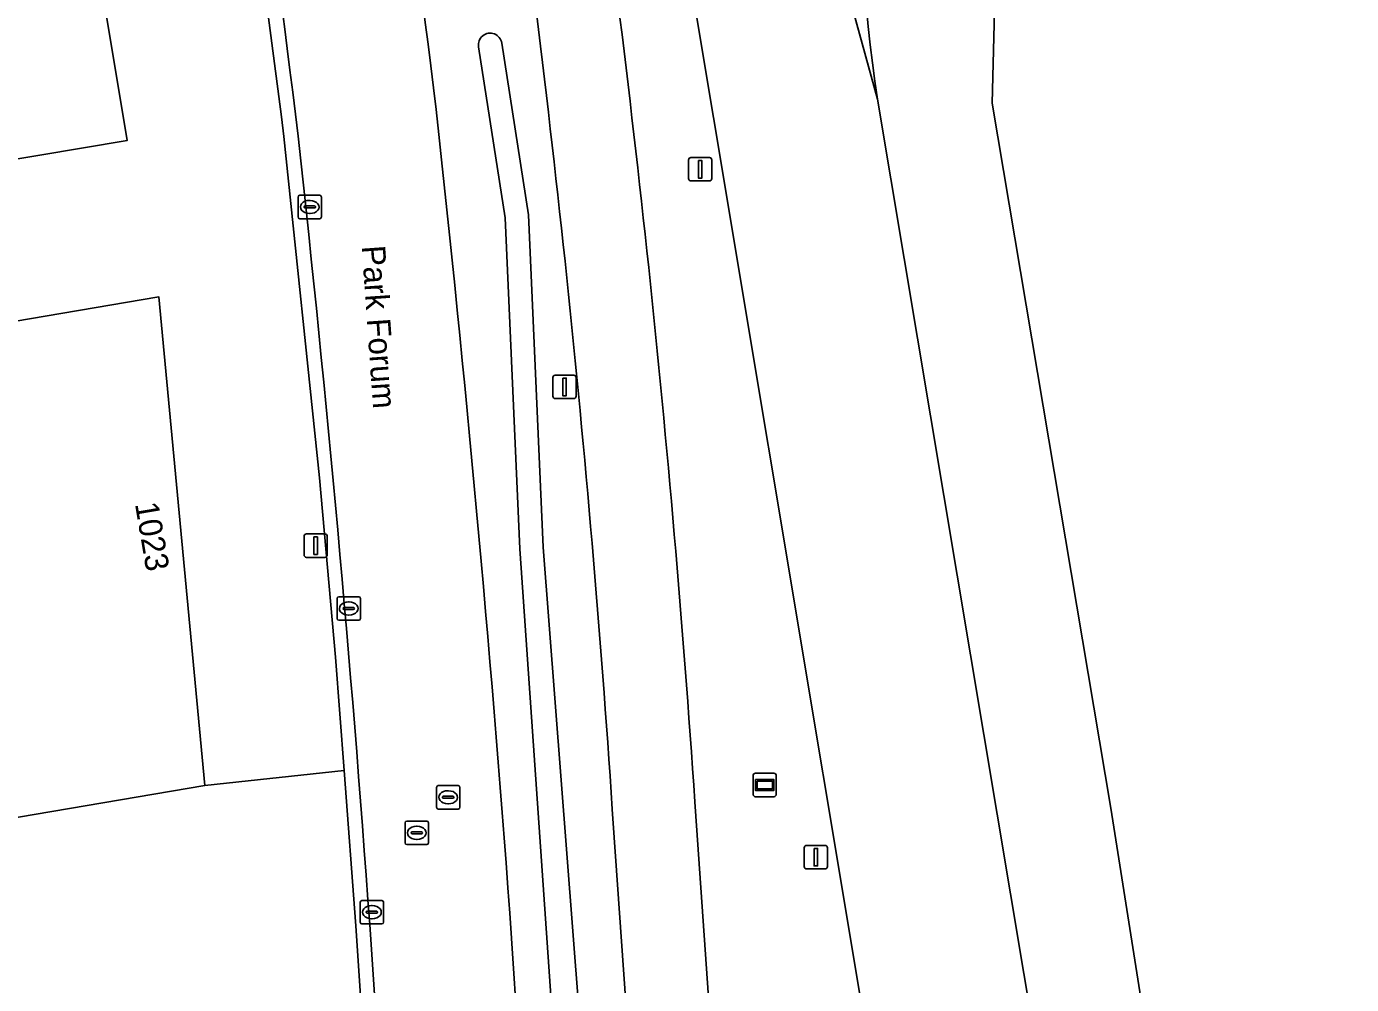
# Model space of a CAD drawing. Extents: x 154324 to 155744, y 382937 to 384188.
# Drawn here: x 155052.1 to 155108.8, y 383387.4 to 383428.3 of the extents above; entities that cross this region are included whole.
import ezdxf

# ---------------------------------------------------------------- set-up
doc = ezdxf.new("R2010")
doc.units = 0
for name, color, linetype in [('IMGEO_Berm_groen', 7, 'Continuous'), ('IMGEO_Erf', 7, 'Continuous'), ('IMGEO_Fietspad_gesloten', 7, 'Continuous'), ('IMGEO_Grasland_agrarisch', 7, 'Continuous'), ('IMGEO_Greppel_droge_sloot', 7, 'Continuous'), ('IMGEO_Groenvoorziening', 7, 'Continuous'), ('IMGEO_Kolk', 7, 'Continuous'), ('IMGEO_Lichtmast', 7, 'Continuous'), ('IMGEO_Loofbos', 7, 'Continuous'), ('IMGEO_Openbare_ruimte_label', 7, 'Continuous'), ('IMGEO_Pand', 7, 'Continuous'), ('IMGEO_Pand_nummerreeks', 7, 'Continuous'), ('IMGEO_Rijbaan_lokaal_gesloten', 7, 'Continuous'), ('IMGEO_Rijbaan_lokaal_open', 7, 'Continuous'), ('IMGEO_Rijbaan_regionaal_gesloten', 7, 'Continuous'), ('IMGEO_Rioolput', 7, 'Continuous'), ('IMGEO_Wegwijzer', 7, 'Continuous')]:
    doc.layers.add(name, color=color, linetype=linetype)

msp = doc.modelspace()

# ---------------------------------------------------------------- linework, layer by layer
at = {"layer": 'IMGEO_Berm_groen'}
for points in [[(155080.698, 383395.149), (155084.447, 383341.596), (155085.067, 383327.696), (155085.135, 383323.941), (155087.898, 383324.309), (155095.535, 383325.326), (155097.848, 383325.634), (155095.519, 383340.332), (155076.819, 383452.367)], [(155076.041, 383365.341), (155073.219, 383405.951), (155072.594, 383420.096), (155071.455, 383427.398)], [(155072.443, 383427.552), (155073.586, 383420.223), (155074.216, 383406.02)], [(155074.216, 383406.02), (155075.741, 383386.313), (155077.04, 383365.403)], [(155081.9, 383290.584), (155081.827, 383312.283), (155081.566, 383327.494), (155080.905, 383341.835), (155077.17, 383394.842)], [(155072.788, 383390.399), (155076.503, 383334.279)]]:
    msp.add_lwpolyline(points, dxfattribs=at)
for centre, radius, start, end in [((154416.191, 383345.471), 658.237, 6.914298, 9.527814), ((154487.454, 383355.336), 594.578, 3.839363, 8.252921), ((154487.732, 383355.709), 590.736, 3.798282, 8.215646), ((155071.949, 383427.475), 0.5, 8.8525, 188.8663), ((154136.569, 383321.838), 938.726, 4.1884, 6.291685)]:
    msp.add_arc(centre, radius, start, end, dxfattribs=at)
at = {"layer": 'IMGEO_Erf'}
for points in [[(155009.132, 383408.441), (155057.795, 383416.713), (155059.756, 383395.855), (155065.709, 383396.485), (155065.341, 383401.33), (155064.659, 383408.986), (155063.139, 383423.564), (155063.03, 383424.403), (155061.613, 383435.27), (155060.487, 383443.041), (155058.846, 383453.397), (155045.918, 383530.449)], [(155044.545, 383443.936), (155052.777, 383445.305), (155054.28, 383436.31), (155053.008, 383436.097), (155053.665, 383432.17), (155054.937, 383432.384), (155056.445, 383423.395), (154989.658, 383412.19)]]:
    msp.add_lwpolyline(points, dxfattribs=at)
at = {"layer": 'IMGEO_Fietspad_gesloten'}
for points in [[(155077.17, 383394.842), (155080.905, 383341.835), (155081.566, 383327.494), (155081.827, 383312.283), (155081.9, 383290.584)], [(155085.424, 383290.508), (155085.346, 383312.247), (155085.135, 383323.941), (155085.067, 383327.696), (155084.447, 383341.596), (155080.698, 383395.149)]]:
    msp.add_lwpolyline(points, dxfattribs=at)
for centre, radius, start, end in [((154487.454, 383355.336), 594.578, 3.839363, 8.252921), ((154487.732, 383355.709), 590.736, 3.798282, 8.215646)]:
    msp.add_arc(centre, radius, start, end, dxfattribs=at)
at = {"layer": 'IMGEO_Grasland_agrarisch'}
msp.add_lwpolyline([(155069.432, 383341.538), (155066.213, 383389.857), (155065.709, 383396.485), (155059.756, 383395.855), (155012.632, 383387.85), (154994.323, 383384.618), (154989.658, 383412.19), (154987.442, 383425.439), (154984.951, 383439.946), (154985.613, 383440.023), (154982.63, 383457.869), (154982.713, 383457.883), (154949.335, 383647.913)], dxfattribs=at)
at = {"layer": 'IMGEO_Greppel_droge_sloot'}
for points in [[(155071.455, 383427.398), (155072.594, 383420.096), (155073.219, 383405.951), (155076.041, 383365.341)], [(155077.04, 383365.403), (155075.741, 383386.313), (155074.216, 383406.02), (155073.586, 383420.223), (155072.443, 383427.552)]]:
    msp.add_lwpolyline(points, dxfattribs=at)
msp.add_arc((155071.949, 383427.475), 0.5, 8.8525, 188.8663, dxfattribs=at)
at = {"layer": 'IMGEO_Groenvoorziening'}
msp.add_lwpolyline([(155098.468, 383394.88), (155093.402, 383424.985), (155093.91, 383445.3), (155100.943, 383462.488), (155107.736, 383471.089), (155129.143, 383483.74), (155137.144, 383484.281), (155140.63, 383467.071), (155136.381, 383463.412), (155137.911, 383457.313), (155135.315, 383439.71), (155145.951, 383434.989), (155156.14, 383427.969), (155169.731, 383420.841), (155156.553, 383398.835), (155144.405, 383376.88), (155136.829, 383369.749), (155130.45, 383360.745), (155130.039, 383352.225), (155124.389, 383342.473), (155103.488, 383363.139)], close=True, dxfattribs=at)
msp.add_lwpolyline([(155088.506, 383425.158), (155097.016, 383374.301)], dxfattribs=at)
msp.add_arc((155150.9, 383434.774), 63.13, 166.13008, 188.76182, dxfattribs=at)
at = {"layer": 'IMGEO_Kolk'}
for p, q in [((155063.742, 383420.127), (155063.742, 383420.979)), ((155063.817, 383421.053), (155064.669, 383421.053)), ((155064.743, 383420.979), (155064.743, 383420.127)), ((155064.001, 383420.547), (155064.001, 383420.559)), ((155064.439, 383420.51), (155064.041, 383420.51)), ((155064.044, 383420.596), (155064.442, 383420.596)), ((155064.23, 383420.833), (155064.255, 383420.833)), ((155064.485, 383420.559), (155064.485, 383420.547)), ((155064.669, 383420.053), (155063.817, 383420.053)), ((155064.253, 383420.273), (155064.228, 383420.273)), ((155065.481, 383403.906), (155066.333, 383403.906)), ((155065.406, 383402.98), (155065.406, 383403.832)), ((155065.665, 383403.4), (155065.665, 383403.412)), ((155066.103, 383403.363), (155065.705, 383403.363)), ((155065.708, 383403.449), (155066.106, 383403.449)), ((155065.894, 383403.686), (155065.919, 383403.686)), ((155066.149, 383403.412), (155066.149, 383403.4)), ((155066.407, 383403.832), (155066.407, 383402.98)), ((155066.333, 383402.906), (155065.481, 383402.906)), ((155065.917, 383403.126), (155065.892, 383403.126)), ((155066.397, 383390.012), (155066.397, 383390.864)), ((155066.472, 383390.938), (155067.324, 383390.938)), ((155067.398, 383390.864), (155067.398, 383390.012)), ((155066.656, 383390.432), (155066.656, 383390.444)), ((155067.094, 383390.395), (155066.696, 383390.395)), ((155066.699, 383390.481), (155067.097, 383390.481)), ((155066.885, 383390.718), (155066.91, 383390.718)), ((155067.14, 383390.444), (155067.14, 383390.432)), ((155067.324, 383389.938), (155066.472, 383389.938)), ((155066.908, 383390.158), (155066.883, 383390.158))]:
    msp.add_line(p, q, dxfattribs=at)
for points in [[(155063.742, 383420.127), (155063.742, 383420.979)], [(155063.817, 383421.053), (155064.669, 383421.053)], [(155064.743, 383420.979), (155064.743, 383420.127)], [(155064.669, 383420.053), (155063.817, 383420.053)], [(155065.481, 383403.906), (155066.333, 383403.906)], [(155065.406, 383402.98), (155065.406, 383403.832)], [(155066.407, 383403.832), (155066.407, 383402.98)], [(155066.333, 383402.906), (155065.481, 383402.906)], [(155066.397, 383390.012), (155066.397, 383390.864)], [(155066.472, 383390.938), (155067.324, 383390.938)], [(155067.398, 383390.864), (155067.398, 383390.012)], [(155067.324, 383389.938), (155066.472, 383389.938)]]:
    msp.add_lwpolyline(points, dxfattribs=at)
for centre, radius, start, end in [((155063.819, 383420.977), 0.0765, 91.552, 178.448), ((155063.819, 383420.977), 0.0765, 91.552, 178.448), ((155064.667, 383420.977), 0.0765, 1.552, 88.448), ((155064.667, 383420.977), 0.0765, 1.552, 88.448), ((155064.041, 383420.556), 0.0403, 85.8775, 175.7526), ((155064.038, 383420.546), 0.0366, 178.938, 274.7102), ((155064.442, 383420.553), 0.043, 264.8664, 352.4533), ((155064.446, 383420.558), 0.0386, 1.7309, 96.639), ((155063.819, 383420.129), 0.0765, 181.552, 268.448), ((155063.819, 383420.129), 0.0765, 181.552, 268.448), ((155064.667, 383420.129), 0.0765, 271.552, 358.448), ((155064.667, 383420.129), 0.0765, 271.552, 358.448), ((155065.483, 383403.83), 0.0765, 91.552, 178.448), ((155065.483, 383403.83), 0.0765, 91.552, 178.448), ((155066.331, 383403.83), 0.0765, 1.552, 88.448), ((155066.331, 383403.83), 0.0765, 1.552, 88.448), ((155065.705, 383403.409), 0.0403, 85.8775, 175.7526), ((155065.702, 383403.399), 0.0366, 178.938, 274.7102), ((155066.106, 383403.406), 0.043, 264.8664, 352.4533), ((155066.11, 383403.411), 0.0386, 1.7309, 96.639), ((155065.483, 383402.982), 0.0765, 181.552, 268.448), ((155065.483, 383402.982), 0.0765, 181.552, 268.448), ((155066.331, 383402.982), 0.0765, 271.552, 358.448), ((155066.331, 383402.982), 0.0765, 271.552, 358.448), ((155066.474, 383390.862), 0.0765, 91.552, 178.448), ((155066.474, 383390.862), 0.0765, 91.552, 178.448), ((155067.322, 383390.862), 0.0765, 1.552, 88.448), ((155067.322, 383390.862), 0.0765, 1.552, 88.448), ((155066.696, 383390.441), 0.0403, 85.8775, 175.7526), ((155066.693, 383390.431), 0.0366, 178.938, 274.7102), ((155067.097, 383390.438), 0.043, 264.8664, 352.4533), ((155067.101, 383390.443), 0.0386, 1.7309, 96.639), ((155066.474, 383390.014), 0.0765, 181.552, 268.448), ((155066.474, 383390.014), 0.0765, 181.552, 268.448), ((155067.322, 383390.014), 0.0765, 271.552, 358.448), ((155067.322, 383390.014), 0.0765, 271.552, 358.448)]:
    msp.add_arc(centre, radius, start, end, dxfattribs=at)
for centre, major_axis, ratio, start_param, end_param in [((155064.229, 383420.553), (-0.387, 0.002), 0.722429, 4.712389, 7.853982), ((155064.254, 383420.553), (-0.39, 0.002), 0.717154, 1.570796, 4.712389), ((155065.893, 383403.406), (-0.387, 0.002), 0.722429, 4.712389, 7.853982), ((155065.918, 383403.406), (-0.39, 0.002), 0.717154, 1.570796, 4.712389), ((155066.884, 383390.438), (-0.387, 0.002), 0.722429, 4.712389, 7.853982), ((155066.909, 383390.438), (-0.39, 0.002), 0.717154, 1.570796, 4.712389)]:
    msp.add_ellipse(centre, major_axis=major_axis, ratio=ratio, start_param=start_param, end_param=end_param, dxfattribs=at)
at = {"layer": 'IMGEO_Lichtmast'}
for p, q in [((155080.432, 383421.763), (155080.432, 383422.563)), ((155080.432, 383422.563), (155080.432, 383421.763)), ((155080.532, 383422.663), (155081.322, 383422.663)), ((155081.322, 383422.663), (155080.532, 383422.663)), ((155081.422, 383422.563), (155081.422, 383421.763)), ((155081.422, 383421.763), (155081.422, 383422.563)), ((155081.322, 383421.663), (155080.532, 383421.663)), ((155080.532, 383421.663), (155081.322, 383421.663)), ((155074.631, 383412.47), (155074.631, 383413.27)), ((155074.631, 383413.27), (155074.631, 383412.47)), ((155074.731, 383413.37), (155075.521, 383413.37)), ((155075.521, 383413.37), (155074.731, 383413.37)), ((155075.621, 383413.27), (155075.621, 383412.47)), ((155075.621, 383412.47), (155075.621, 383413.27)), ((155075.521, 383412.37), (155074.731, 383412.37)), ((155074.731, 383412.37), (155075.521, 383412.37)), ((155063.998, 383405.692), (155063.998, 383406.492)), ((155063.998, 383406.492), (155063.998, 383405.692)), ((155064.098, 383406.592), (155064.888, 383406.592)), ((155064.888, 383406.592), (155064.098, 383406.592)), ((155064.988, 383406.492), (155064.988, 383405.692)), ((155064.988, 383405.692), (155064.988, 383406.492)), ((155064.888, 383405.592), (155064.098, 383405.592)), ((155064.098, 383405.592), (155064.888, 383405.592)), ((155085.371, 383392.388), (155085.371, 383393.188)), ((155085.371, 383393.188), (155085.371, 383392.388)), ((155085.471, 383393.288), (155086.261, 383393.288)), ((155086.261, 383393.288), (155085.471, 383393.288)), ((155086.361, 383393.188), (155086.361, 383392.388)), ((155086.361, 383392.388), (155086.361, 383393.188)), ((155086.261, 383392.288), (155085.471, 383392.288)), ((155085.471, 383392.288), (155086.261, 383392.288))]:
    msp.add_line(p, q, dxfattribs=at)
for points in [[(155080.852, 383422.538), (155081.002, 383422.538), (155081.002, 383421.788), (155080.852, 383421.788), (155080.852, 383422.538)], [(155075.051, 383413.245), (155075.201, 383413.245), (155075.201, 383412.495), (155075.051, 383412.495), (155075.051, 383413.245)], [(155064.418, 383406.467), (155064.568, 383406.467), (155064.568, 383405.717), (155064.418, 383405.717), (155064.418, 383406.467)], [(155085.791, 383393.163), (155085.941, 383393.163), (155085.941, 383392.413), (155085.791, 383392.413), (155085.791, 383393.163)]]:
    msp.add_lwpolyline(points, dxfattribs=at)
for centre, start, end in [((155080.532, 383422.563), 90, 180), ((155080.532, 383422.563), 90, 180), ((155081.322, 383422.563), 0, 90), ((155081.322, 383422.563), 360, 90), ((155080.532, 383421.763), 180, 270), ((155080.532, 383421.763), 180, 270), ((155081.322, 383421.763), 270, 0), ((155081.322, 383421.763), 270, 0), ((155074.731, 383413.27), 90, 180), ((155074.731, 383413.27), 90, 180), ((155075.521, 383413.27), 0, 90), ((155075.521, 383413.27), 360, 90), ((155074.731, 383412.47), 180, 270), ((155074.731, 383412.47), 180, 270), ((155075.521, 383412.47), 270, 0), ((155075.521, 383412.47), 270, 0), ((155064.098, 383406.492), 90, 180), ((155064.098, 383406.492), 90, 180), ((155064.888, 383406.492), 0, 90), ((155064.888, 383406.492), 360, 90), ((155064.098, 383405.692), 180, 270), ((155064.098, 383405.692), 180, 270), ((155064.888, 383405.692), 270, 0), ((155064.888, 383405.692), 270, 0), ((155085.471, 383393.188), 90, 180), ((155085.471, 383393.188), 90, 180), ((155086.261, 383393.188), 0, 90), ((155086.261, 383393.188), 360, 90), ((155085.471, 383392.388), 180, 270), ((155085.471, 383392.388), 180, 270), ((155086.261, 383392.388), 270, 0), ((155086.261, 383392.388), 270, 0)]:
    msp.add_arc(centre, 0.1, start, end, dxfattribs=at)
at = {"layer": 'IMGEO_Loofbos'}
msp.add_lwpolyline([(155130.039, 383352.225), (155130.45, 383360.745), (155136.829, 383369.749), (155144.405, 383376.88), (155156.553, 383398.835), (155169.731, 383420.841), (155156.14, 383427.969), (155145.951, 383434.989), (155135.315, 383439.71), (155137.911, 383457.313), (155136.381, 383463.412), (155140.63, 383467.071), (155137.144, 383484.281), (155129.143, 383483.74), (155107.736, 383471.089), (155100.943, 383462.488), (155093.91, 383445.3), (155093.402, 383424.985), (155098.468, 383394.88), (155103.488, 383363.139), (155124.389, 383342.473)], close=True, dxfattribs=at)
at = {"layer": 'IMGEO_Pand'}
for points in [[(155054.937, 383432.384), (155053.665, 383432.17), (155053.008, 383436.097), (155054.28, 383436.31), (155052.777, 383445.305), (155044.545, 383443.936), (155044.599, 383443.611), (155045.151, 383443.703), (155045.605, 383440.97), (155040.407, 383440.106), (155015.086, 383435.797), (155016.017, 383430.255), (154987.442, 383425.439), (154989.658, 383412.19), (155056.445, 383423.395)], [(155057.795, 383416.713), (155009.132, 383408.441), (155012.632, 383387.85), (155059.756, 383395.855)]]:
    msp.add_lwpolyline(points, close=True, dxfattribs=at)
at = {"layer": 'IMGEO_Rijbaan_lokaal_gesloten'}
for points in [[(155076.503, 383334.279), (155072.788, 383390.399)], [(155066.805, 383389.917), (155070.546, 383334.082)]]:
    msp.add_lwpolyline(points, dxfattribs=at)
for centre, radius, start, end in [((154416.191, 383345.471), 658.237, 6.914298, 9.527814), ((154372.74, 383339.354), 696.116, 6.949521, 9.434678), ((154136.569, 383321.838), 938.726, 4.1884, 6.291685), ((154201.434, 383328.122), 867.574, 4.08448, 6.316961)]:
    msp.add_arc(centre, radius, start, end, dxfattribs=at)
at = {"layer": 'IMGEO_Rijbaan_lokaal_open'}
for points in [[(155059.439, 383453.463), (155046.503, 383530.572), (155016.871, 383707.197), (155016.277, 383707.107), (155024.164, 383660.104), (155045.918, 383530.449), (155058.846, 383453.397), (155060.487, 383443.041), (155061.613, 383435.27), (155063.03, 383424.403), (155063.139, 383423.564), (155064.659, 383408.986), (155065.341, 383401.33), (155065.709, 383396.485), (155066.213, 383389.857), (155069.432, 383341.538), (155069.458, 383341.15), (155069.938, 383333.947), (155070.4, 383319.494), (155070.638, 383289.04), (155071.247, 383289.042), (155071.154, 383307.067)], [(155070.546, 383334.082), (155066.805, 383389.917)]]:
    msp.add_lwpolyline(points, dxfattribs=at)
for centre, radius, start, end in [((154372.74, 383339.354), 696.116, 6.949521, 9.434678), ((154201.434, 383328.122), 867.574, 4.08448, 6.316961)]:
    msp.add_arc(centre, radius, start, end, dxfattribs=at)
at = {"layer": 'IMGEO_Rijbaan_regionaal_gesloten'}
for points in [[(155088.506, 383425.158), (155082.147, 383448.215), (155075.664, 383486.308), (155070.593, 383489.047), (155071.187, 383485.369), (155076.819, 383452.367), (155095.519, 383340.332), (155097.848, 383325.634), (155099.567, 383313.904), (155107.952, 383291.229), (155108.58, 383289.319), (155109.574, 383286.695)], [(155082.147, 383448.215), (155088.506, 383425.158)], [(155097.016, 383374.301), (155088.506, 383425.158)]]:
    msp.add_lwpolyline(points, dxfattribs=at)
msp.add_arc((155150.9, 383434.774), 63.13, 166.13008, 188.76182, dxfattribs=at)
at = {"layer": 'IMGEO_Rioolput'}
for p, q in [((155069.656, 383394.918), (155069.656, 383395.77)), ((155069.731, 383395.844), (155070.583, 383395.844)), ((155069.958, 383395.387), (155070.356, 383395.387)), ((155070.144, 383395.624), (155070.169, 383395.624)), ((155070.657, 383395.77), (155070.657, 383394.918)), ((155070.583, 383394.844), (155069.731, 383394.844)), ((155069.915, 383395.338), (155069.915, 383395.35)), ((155070.353, 383395.301), (155069.955, 383395.301)), ((155070.167, 383395.064), (155070.142, 383395.064)), ((155070.399, 383395.35), (155070.399, 383395.338)), ((155068.313, 383393.402), (155068.313, 383394.254)), ((155068.388, 383394.328), (155069.24, 383394.328)), ((155069.314, 383394.254), (155069.314, 383393.402)), ((155068.572, 383393.822), (155068.572, 383393.834)), ((155069.01, 383393.785), (155068.612, 383393.785)), ((155068.615, 383393.871), (155069.013, 383393.871)), ((155068.801, 383394.108), (155068.826, 383394.108)), ((155069.056, 383393.834), (155069.056, 383393.822)), ((155069.24, 383393.328), (155068.388, 383393.328)), ((155068.824, 383393.548), (155068.799, 383393.548))]:
    msp.add_line(p, q, dxfattribs=at)
for points in [[(155069.656, 383394.918), (155069.656, 383395.77)], [(155069.731, 383395.844), (155070.583, 383395.844)], [(155070.657, 383395.77), (155070.657, 383394.918)], [(155070.583, 383394.844), (155069.731, 383394.844)], [(155068.313, 383393.402), (155068.313, 383394.254)], [(155068.388, 383394.328), (155069.24, 383394.328)], [(155069.314, 383394.254), (155069.314, 383393.402)], [(155069.24, 383393.328), (155068.388, 383393.328)]]:
    msp.add_lwpolyline(points, dxfattribs=at)
for centre, radius, start, end in [((155069.733, 383395.768), 0.0765, 91.552, 178.448), ((155069.733, 383395.768), 0.0765, 91.552, 178.448), ((155069.955, 383395.347), 0.0403, 85.8775, 175.7526), ((155070.36, 383395.349), 0.0386, 1.7309, 96.639), ((155070.581, 383395.768), 0.0765, 1.552, 88.448), ((155070.581, 383395.768), 0.0765, 1.552, 88.448), ((155069.733, 383394.92), 0.0765, 181.552, 268.448), ((155069.733, 383394.92), 0.0765, 181.552, 268.448), ((155069.952, 383395.337), 0.0366, 178.938, 274.7102), ((155070.356, 383395.344), 0.043, 264.8664, 352.4533), ((155070.581, 383394.92), 0.0765, 271.552, 358.448), ((155070.581, 383394.92), 0.0765, 271.552, 358.448), ((155068.39, 383394.252), 0.0765, 91.552, 178.448), ((155068.39, 383394.252), 0.0765, 91.552, 178.448), ((155069.238, 383394.252), 0.0765, 1.552, 88.448), ((155069.238, 383394.252), 0.0765, 1.552, 88.448), ((155068.612, 383393.831), 0.0403, 85.8775, 175.7526), ((155068.609, 383393.821), 0.0366, 178.938, 274.7102), ((155069.013, 383393.828), 0.043, 264.8664, 352.4533), ((155069.017, 383393.833), 0.0386, 1.7309, 96.639), ((155068.39, 383393.404), 0.0765, 181.552, 268.448), ((155068.39, 383393.404), 0.0765, 181.552, 268.448), ((155069.238, 383393.404), 0.0765, 271.552, 358.448), ((155069.238, 383393.404), 0.0765, 271.552, 358.448)]:
    msp.add_arc(centre, radius, start, end, dxfattribs=at)
for centre, major_axis, ratio, start_param, end_param in [((155070.143, 383395.344), (-0.387, 0.002), 0.722429, 4.712389, 7.853982), ((155070.168, 383395.344), (-0.39, 0.002), 0.717154, 1.570796, 4.712389), ((155068.8, 383393.828), (-0.387, 0.002), 0.722429, 4.712389, 7.853982), ((155068.825, 383393.828), (-0.39, 0.002), 0.717154, 1.570796, 4.712389)]:
    msp.add_ellipse(centre, major_axis=major_axis, ratio=ratio, start_param=start_param, end_param=end_param, dxfattribs=at)
at = {"layer": 'IMGEO_Wegwijzer'}
for p, q in [((155083.188, 383395.471), (155083.188, 383396.271)), ((155083.188, 383396.271), (155083.188, 383395.471)), ((155083.288, 383396.371), (155084.078, 383396.371)), ((155084.078, 383396.371), (155083.288, 383396.371)), ((155084.178, 383396.271), (155084.178, 383395.471)), ((155084.178, 383395.471), (155084.178, 383396.271)), ((155084.078, 383395.371), (155083.288, 383395.371)), ((155083.288, 383395.371), (155084.078, 383395.371))]:
    msp.add_line(p, q, dxfattribs=at)
for points in [[(155083.289, 383396.103), (155084.077, 383396.103), (155084.077, 383395.639), (155083.289, 383395.639), (155083.289, 383396.103)], [(155083.354, 383396.038), (155083.354, 383395.704), (155084.012, 383395.704), (155084.012, 383396.038), (155083.354, 383396.038)]]:
    msp.add_lwpolyline(points, dxfattribs=at)
for centre, start, end in [((155083.288, 383396.271), 90, 180), ((155083.288, 383396.271), 90, 180), ((155084.078, 383396.271), 0, 90), ((155084.078, 383396.271), 360, 90), ((155083.288, 383395.471), 180, 270), ((155083.288, 383395.471), 180, 270), ((155084.078, 383395.471), 270, 0), ((155084.078, 383395.471), 270, 0)]:
    msp.add_arc(centre, 0.1, start, end, dxfattribs=at)

# ---------------------------------------------------------------- texts
at = {"layer": 'IMGEO_Openbare_ruimte_label'}
msp.add_text('Park Forum', height=1, rotation=274.0122, dxfattribs=at).set_placement((155066.461, 383418.881))
at = {"layer": 'IMGEO_Pand_nummerreeks'}
msp.add_text('1023', height=1, rotation=279.6427, dxfattribs=at).set_placement((155056.768, 383407.874))

doc.saveas('drawing.dxf')
